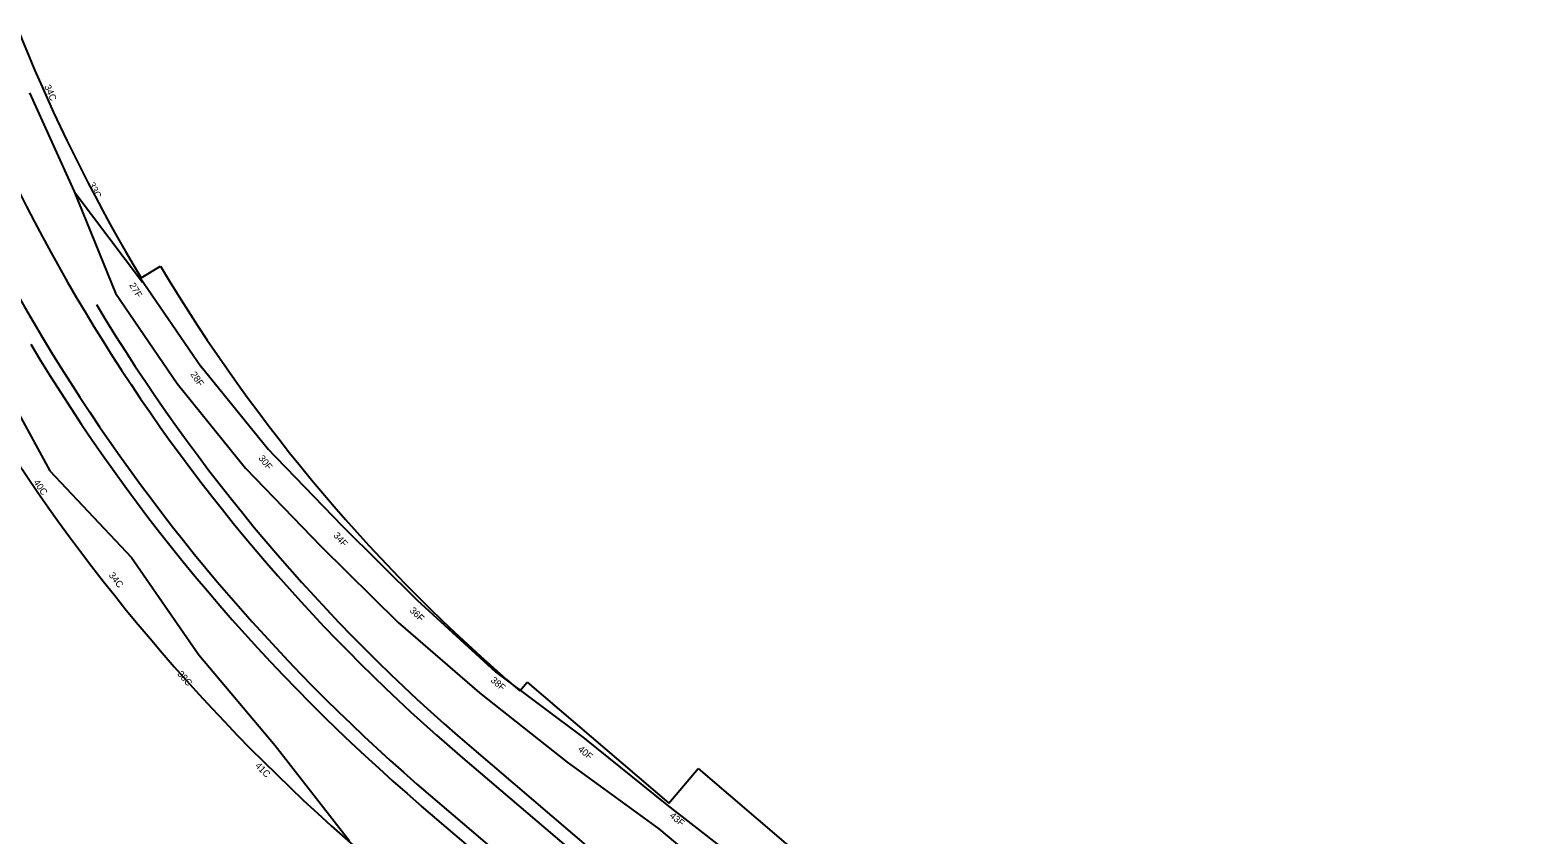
# Model space of a CAD drawing. Extents: x 2006539 to 2009039, y 1001971 to 1004377.
# Drawn here: x 2007375 to 2008043, y 1003166 to 1003522 of the extents above; entities that cross this region are included whole.
import ezdxf

# ---------------------------------------------------------------- set-up
doc = ezdxf.new("R2010")
doc.units = 0
for name, color, linetype in [('RD_PD_CstnLmt', 7, 'Continuous'), ('RD_PD_CstnLmt_TX', 7, 'Continuous'), ('RD_PD_DR_ErosCtrl', 7, 'Continuous'), ('RD_PD_Final_TrvlWay', 7, 'Continuous'), ('RD_PD_GR', 7, 'Continuous'), ('RD_PD_RW', 7, 'Continuous')]:
    doc.layers.add(name, color=color, linetype=linetype)

msp = doc.modelspace()

# ---------------------------------------------------------------- linework, layer by layer
at = {"layer": 'RD_PD_CstnLmt'}
for p, q in [((2007375.17, 1003494.65), (2007394.91, 1003450.95)), ((2007394.91, 1003450.95), (2007413.13, 1003405.96)), ((2007413.13, 1003405.96), (2007440.44, 1003366.1)), ((2007358.88, 1003373.64), (2007384.06, 1003327.39)), ((2007440.44, 1003366.1), (2007470.8, 1003328.61)), ((2007384.06, 1003327.39), (2007420.27, 1003289.11)), ((2007470.8, 1003328.61), (2007504.23, 1003293.98)), ((2007504.23, 1003293.98), (2007538.3, 1003260.35)), ((2007420.27, 1003289.11), (2007450.06, 1003245.97)), ((2007538.3, 1003260.35), (2007574.44, 1003229.11)), ((2007450.06, 1003245.97), (2007483.94, 1003205.83)), ((2007574.44, 1003229.11), (2007613.16, 1003198.44)), ((2007483.94, 1003205.83), (2007516.74, 1003163.62)), ((2007613.16, 1003198.44), (2007653.79, 1003169.02)), ((2007653.79, 1003169.02), (2007692.14, 1003136.94))]:
    msp.add_line(p, q, dxfattribs=at)
at = {"layer": 'RD_PD_DR_ErosCtrl'}
for p, q in [((2007394.91, 1003450.95), (2007425.18, 1003410.85)), ((2007423.85, 1003413.31), (2007451.17, 1003373.45)), ((2007450.55, 1003374.29), (2007480.9, 1003336.8)), ((2007480.16, 1003337.64), (2007513.58, 1003303.01)), ((2007513.36, 1003303.23), (2007547.43, 1003269.6)), ((2007546.8, 1003270.18), (2007581.42, 1003238.38)), ((2007581.42, 1003238.38), (2007621.24, 1003208.63)), ((2007620.79, 1003208.97), (2007657.3, 1003179.54)), ((2007657.3, 1003179.54), (2007710.01, 1003138.8))]:
    msp.add_line(p, q, dxfattribs=at)
at = {"layer": 'RD_PD_Final_TrvlWay'}
for p, q in [((2007566.9, 1003200.38), (2008001.5, 1002830.16)), ((2007552.64, 1003183.64), (2007987.23, 1002813.41))]:
    msp.add_line(p, q, dxfattribs=at)
for radius in [799.87, 821.87]:
    msp.add_arc((2008085.61, 1003809.27), radius, 194.53337, 229.57273, dxfattribs=at)
at = {"layer": 'RD_PD_GR'}
for p, q in [((2007570.79, 1003204.95), (2007676.21, 1003115.15)), ((2007654.16, 1003089.27), (2007548.75, 1003179.07))]:
    msp.add_line(p, q, dxfattribs=at)
for radius in [793.87, 827.87]:
    msp.add_arc((2008085.61, 1003809.27), radius, 210.95245, 229.57273, dxfattribs=at)
at = {"layer": 'RD_PD_RW'}
for p, q in [((2007424.51, 1003412.79), (2007433.09, 1003417.93)), ((2007592.19, 1003230.07), (2007595.44, 1003233.88)), ((2007595.44, 1003233.88), (2007658.22, 1003180.39)), ((2007658.22, 1003180.39), (2007671.19, 1003195.62)), ((2007671.19, 1003195.62), (2008043, 1002878.88))]:
    msp.add_line(p, q, dxfattribs=at)
for radius, start, end in [(770.87, 194.53337, 210.95245), (860.87, 194.53337, 229.57273), (760.87, 210.95245, 229.57273)]:
    msp.add_arc((2008085.61, 1003809.27), radius, start, end, dxfattribs=at)

# ---------------------------------------------------------------- texts
at = {"layer": 'RD_PD_CstnLmt_TX'}
for s, rotation, p in [('34C', 293.88653, (2007381.57, 1003497.48)), ('33C', 297.41949, (2007401.12, 1003454.17)), ('27F', 300.95245, (2007419.13, 1003409.57)), ('28F', 304.48541, (2007446.21, 1003370.07)), ('30F', 308.01837, (2007476.32, 1003332.93)), ('40C', 304.48541, (2007376.69, 1003322.31)), ('34F', 311.55133, (2007509.47, 1003298.62)), ('34C', 308.01837, (2007410.03, 1003281.1)), ('36F', 315.08429, (2007543.24, 1003265.31)), ('38C', 311.55133, (2007440.34, 1003237.35)), ('38F', 318.61725, (2007579.06, 1003234.36)), ('40F', 319.57273, (2007617.7, 1003203.77)), ('41C', 315.08429, (2007474.76, 1003196.62)), ('43F', 319.57273, (2007658.33, 1003174.35))]:
    msp.add_text(s, height=3, rotation=rotation, dxfattribs=at).set_placement(p)

doc.saveas('drawing.dxf')
